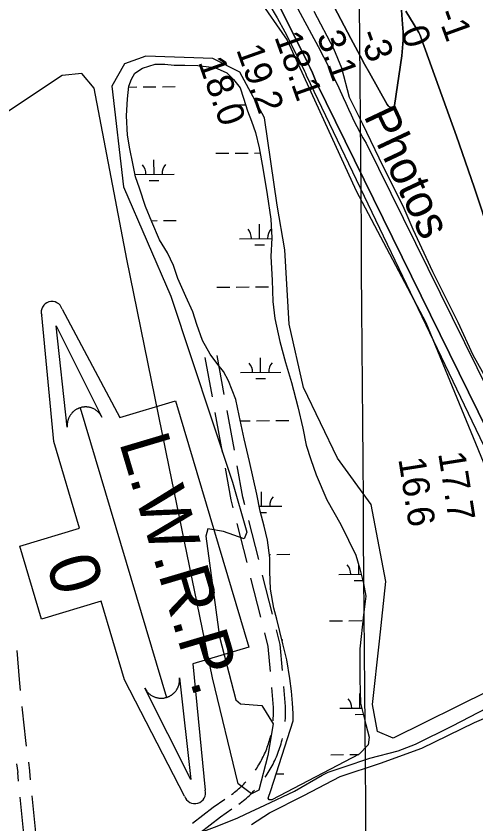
# Model space of a CAD drawing. Extents: x 3540316 to 3578335, y 553172 to 578787.
# Drawn here: x 3548915 to 3550058, y 559700 to 561708 of the extents above; entities that cross this region are included whole.
import ezdxf

# ---------------------------------------------------------------- set-up
doc = ezdxf.new("R2010")
doc.units = 0
for name, color, linetype in [('V-DTCH-CNTR', 7, 'Continuous'), ('V-GRID-MAJR', 7, 'Continuous'), ('V-RIVR-EDGE', 7, 'Continuous'), ('V-RIVR-IDEN', 7, 'Continuous'), ('V-RIVR-RANG', 7, 'Continuous'), ('V-ROAD-CNTR', 7, 'Continuous'), ('V-SITE-VEGE', 7, 'Continuous'), ('V-TOPO-DPTH', 7, 'Continuous'), ('V-TOPO-MINR', 7, 'Continuous'), ('V-TOPO-WATR', 7, 'Continuous'), ('V-TOPO-WATR-IDEN', 7, 'Continuous'), ('V-WETL-SWMP', 7, 'Continuous')]:
    doc.layers.add(name, color=color, linetype=linetype)

msp = doc.modelspace()

# ---------------------------------------------------------------- linework, layer by layer
at = {"layer": 'V-DTCH-CNTR'}
for points in [[(3549485, 559724.9), (3549533.4, 559746.8), (3549607.2, 559781.4), (3549675.8, 559821.1), (3549691.1, 559828.6), (3549730.9, 559841.8), (3549794.2, 559863.8), (3549865, 559882.3), (3549908.4, 559898.3), (3550000.5, 559944), (3550086.8, 559988.4), (3550165.2, 560026.6), (3550230.1, 560057.2)], [(3549012.5, 559549), (3549102.4, 559580.2), (3549225.7, 559624.1), (3549334.7, 559665.2), (3549361.7, 559675.1), (3549415.1, 559694.7), (3549466.2, 559715.4), (3549485, 559724.9)]]:
    msp.add_lwpolyline(points, dxfattribs=at)
at = {"layer": 'V-GRID-MAJR'}
msp.add_spline([(3549793, 558613.9), (3549748.1, 564672.9), (3549703.1, 570733.8), (3549658.2, 576794.8), (3549658.2, 576796.7)], degree=3, dxfattribs=at)
at = {"layer": 'V-RIVR-EDGE'}
msp.add_lwpolyline([(3549655.4, 561719.8), (3549704.4, 561627.2), (3549724.1, 561579.2), (3549743.1, 561506.5), (3549776.6, 561439.8), (3549827.3, 561335.2), (3549876.3, 561236.6), (3549901.4, 561178.3), (3549950.4, 561073.1), (3550013.7, 560947.5), (3550050.7, 560866.4), (3550104.5, 560769.6)], dxfattribs=at)
at = {"layer": 'V-ROAD-CNTR'}
for points in [[(3549403, 560761.8), (3549385.3, 560859.4)], [(3549432.5, 560767.2), (3549414.8, 560864.7)], [(3549428, 560624.1), (3549410.1, 560722.5)], [(3549457.5, 560629.4), (3549439.7, 560727.8)], [(3549483.7, 560493), (3549478.8, 560512), (3549464.7, 560590.1)], [(3549454.6, 560485.6), (3549449.5, 560505.6), (3549435.1, 560584.7)], [(3549518.1, 560357.3), (3549493.5, 560454.2)], [(3549489, 560349.9), (3549464.4, 560446.8)], [(3549523.4, 560214.2), (3549498.8, 560311.1)], [(3549552.5, 560221.6), (3549527.9, 560318.5)], [(3549547.1, 560079.2), (3549542, 560141), (3549533.2, 560175.4)], [(3549577, 560081.7), (3549571.6, 560146), (3549562.3, 560182.8)], [(3548916.2, 560131.2), (3548922.2, 560059.5), (3548924.8, 560031.8)], [(3549554.5, 559989.5), (3549550.4, 560039.3)], [(3549584.4, 559992), (3549580.3, 560041.8)], [(3548928.6, 559992), (3548929.4, 559983.6), (3548937.9, 559907.8), (3548939.9, 559893.2)], [(3549553.9, 559956.8), (3549554.1, 559959.5), (3549554.4, 559963.9), (3549554.6, 559968.3), (3549554.7, 559972.7), (3549554.8, 559977.1), (3549554.8, 559981.5), (3549554.6, 559985.8), (3549554.5, 559990.2)], [(3549583.8, 559954.5), (3549584.1, 559957.4), (3549584.4, 559962.3), (3549584.6, 559967.2), (3549584.7, 559972.1), (3549584.8, 559977), (3549584.8, 559982), (3549584.6, 559986.9), (3549584.4, 559991.3)], [(3549509.8, 559833.9), (3549511.5, 559836.4), (3549513.9, 559840), (3549516.3, 559843.7), (3549518.6, 559847.5), (3549520.8, 559851.2), (3549523, 559855.1), (3549525.1, 559858.9), (3549527.1, 559862.8), (3549529.1, 559866.7), (3549531, 559870.7), (3549532.8, 559874.7), (3549534.6, 559878.7), (3549536.3, 559882.8), (3549537.9, 559886.8), (3549539.4, 559891), (3549540.9, 559895.1), (3549542.3, 559899.3), (3549543.6, 559903.5), (3549544.9, 559907.7), (3549546.1, 559911.9), (3549547.2, 559916.2), (3549548.1, 559919.7)], [(3549534.5, 559816.8), (3549536.3, 559819.5), (3549539.1, 559823.6), (3549541.7, 559827.8), (3549544.3, 559831.9), (3549546.8, 559836.2), (3549549.2, 559840.5), (3549551.6, 559844.8), (3549553.8, 559849.1), (3549556.1, 559853.5), (3549558.2, 559858), (3549560.2, 559862.4), (3549562.2, 559866.9), (3549564.1, 559871.5), (3549565.9, 559876.1), (3549567.6, 559880.7), (3549569.3, 559885.3), (3549570.8, 559890), (3549572.3, 559894.7), (3549573.7, 559899.3), (3549575.1, 559904.1), (3549576.3, 559908.9), (3549577.2, 559912.6)], [(3548915.6, 559849.5), (3548918.5, 559827.8)], [(3548945.3, 559853.6), (3548948.2, 559831.8)], [(3548920.6, 559806.7), (3548918.5, 559828.3)], [(3548950.4, 559809.7), (3548948.3, 559831.3)], [(3549450.6, 559773.5), (3549454.2, 559776.2), (3549457.6, 559778.8), (3549461.1, 559781.6), (3549464.5, 559784.4), (3549467.8, 559787.2), (3549471.1, 559790.1), (3549474.4, 559793.1), (3549477.6, 559796.1), (3549480.7, 559799.1), (3549483.8, 559802.3), (3549486.1, 559804.7)], [(3548934.3, 559667.4), (3548924.5, 559766.9)], [(3548964.2, 559670.4), (3548954.4, 559769.9)], [(3549468.3, 559749.3), (3549472.2, 559752.2), (3549476.1, 559755.2), (3549479.9, 559758.2), (3549483.7, 559761.3), (3549487.5, 559764.5), (3549491.1, 559767.8), (3549494.8, 559771.1), (3549498.4, 559774.5), (3549501.9, 559777.9), (3549505.4, 559781.4), (3549507.8, 559784)], [(3549353.3, 559701.9), (3549405.1, 559741.7), (3549434, 559761.9)], [(3549371.5, 559678.1), (3549422.8, 559717.5), (3549451.2, 559737.4)]]:
    msp.add_lwpolyline(points, dxfattribs=at)
at = {"layer": 'V-SITE-VEGE'}
for p, q in [((3549317.9, 562039.3), (3549589, 561647.7)), ((3549589, 561647.7), (3549760.5, 561274)), ((3549237.5, 561608.3), (3549184.4, 561589.4)), ((3549404.1, 561602.5), (3549237.5, 561608.3)), ((3549471.5, 561568.2), (3549404.1, 561602.5)), ((3549184.4, 561589.4), (3549152.3, 561533.7)), ((3549029.5, 561560.6), (3548829, 561427.3)), ((3549078.1, 561565.6), (3549029.5, 561560.6)), ((3549108.4, 561528.8), (3549078.1, 561565.6)), ((3549532.4, 561455.2), (3549471.5, 561568.2)), ((3549152.3, 561533.7), (3549181.8, 561283.9)), ((3549190, 561103.5), (3549108.4, 561528.8)), ((3549564, 561237.9), (3549532.4, 561455.2)), ((3549181.8, 561283.9), (3549299.4, 561011.6)), ((3549760.5, 561274), (3549933.9, 560946.5)), ((3549583.2, 561127), (3549564, 561237.9)), ((3549593.8, 560941.9), (3549583.2, 561127)), ((3549295.3, 560588.1), (3549190, 561103.5)), ((3549299.4, 561011.6), (3549452.9, 560549.8)), ((3549629.5, 560784.7), (3549593.8, 560941.9)), ((3549933.9, 560946.5), (3550148.1, 560424.9)), ((3549714, 560609.4), (3549629.5, 560784.7)), ((3549798.1, 560494.3), (3549714, 560609.4)), ((3549403, 560063.4), (3549295.3, 560588.1)), ((3549452.9, 560549.8), (3549488.5, 560425.1)), ((3549834.2, 560302.4), (3549798.1, 560494.3)), ((3549391.2, 560433.7), (3549386.7, 560415.1)), ((3549430.6, 560427), (3549391.2, 560433.7)), ((3549386.7, 560415.1), (3549420.8, 560165.4)), ((3549481.6, 560408.8), (3549430.6, 560427)), ((3549488.5, 560425.1), (3549481.6, 560408.8)), ((3549819, 560154.2), (3549834.2, 560302.4)), ((3549420.8, 560165.4), (3549461.2, 560008.3)), ((3549801.5, 559996.7), (3549819, 560154.2)), ((3549467.3, 559800), (3549403, 560063.4)), ((3550090.6, 560031.1), (3549853, 559913.7)), ((3550055.2, 559952.1), (3550238.7, 560032.1)), ((3549461.2, 560008.3), (3549472.9, 559999.1)), ((3549472.9, 559999.1), (3549526.1, 559994.8)), ((3549526.1, 559994.8), (3549554.2, 559948.8)), ((3549813.5, 559929.7), (3549801.5, 559996.7)), ((3549554.2, 559948.8), (3549540.8, 559870)), ((3549924.3, 559888.2), (3550055.2, 559952.1)), ((3549853, 559913.7), (3549813.5, 559929.7)), ((3549821, 559851.6), (3549924.3, 559888.2)), ((3549540.8, 559870), (3549518.3, 559784.2)), ((3549721.1, 559818), (3549821, 559851.6)), ((3549630, 559771.1), (3549721.1, 559818)), ((3549499.8, 559774.8), (3549467.3, 559800)), ((3549518.3, 559784.2), (3549499.8, 559774.8)), ((3549544.7, 559727.7), (3549630, 559771.1)), ((3549499.8, 559699), (3549544.7, 559727.7))]:
    msp.add_line(p, q, dxfattribs=at)
at = {"layer": 'V-TOPO-DPTH'}
for points in [[(3549873.2, 561722.5), (3549876.1, 561687.9), (3549877.1, 561668.2), (3549877.2, 561648.6), (3549876, 561629), (3549873.9, 561609.4), (3549856.3, 561485.7), (3549855.2, 561483.1), (3549853.5, 561481.2), (3549851.1, 561480.3), (3549848.3, 561480.1), (3549845, 561481.3), (3549842.1, 561482.9), (3549839.8, 561485.2), (3549837.7, 561487.9), (3549793.5, 561567), (3549781.7, 561588.2), (3549770.1, 561609.4), (3549758.7, 561630.7), (3549747.4, 561652), (3549581.8, 561967.8)], [(3549581.8, 561967.8), (3549747.4, 561652), (3549758.7, 561630.7), (3549770.1, 561609.4), (3549781.7, 561588.2), (3549793.5, 561567), (3549837.7, 561487.9), (3549839.8, 561485.2), (3549842.1, 561482.9), (3549845, 561481.3), (3549848.3, 561480.1), (3549851.1, 561480.3), (3549853.5, 561481.2), (3549855.2, 561483.1), (3549856.3, 561485.7), (3549873.9, 561609.4), (3549876, 561629), (3549877.2, 561648.6), (3549877.1, 561668.2), (3549876.1, 561687.9), (3549873.2, 561722.5)], [(3550158.9, 560532.2), (3549661.8, 561541.8), (3549656.9, 561554.4), (3549651.8, 561566.8), (3549646.3, 561579.1), (3549640.5, 561591.2), (3549558.2, 561757)], [(3550096.2, 561154.8), (3550054.2, 561282.5), (3550010.2, 561409.6), (3549922.5, 561653.2), (3549920.6, 561657.9), (3549918.6, 561662.5), (3549916.3, 561667), (3549913.8, 561671.4), (3549884.4, 561720.3)], [(3549884.4, 561720.3), (3549913.8, 561671.4), (3549916.3, 561667), (3549918.6, 561662.5), (3549920.6, 561657.9), (3549922.5, 561653.2), (3550010.2, 561409.6), (3550054.2, 561282.5), (3550096.2, 561154.8)]]:
    msp.add_lwpolyline(points, dxfattribs=at)
at = {"layer": 'V-TOPO-MINR'}
for points in [[(3549420.2, 562087), (3549665.8, 561632.5), (3549679.3, 561607), (3549692.5, 561581.3), (3549705.2, 561555.4), (3549717.5, 561529.3), (3549728.3, 561506), (3549735, 561491.5), (3549741.7, 561476.9), (3549748.4, 561462.4), (3549755, 561447.9), (3549762, 561433.5), (3549769.3, 561419.3), (3549777.3, 561405.5), (3549785.6, 561391.9), (3550183.1, 560586.4)], [(3549558.2, 561757), (3549640.5, 561591.2), (3549646.3, 561579.1), (3549651.8, 561566.8), (3549656.9, 561554.4), (3549661.8, 561541.8), (3550158.9, 560532.2)], [(3549543.5, 561738.6), (3549563.7, 561704), (3549582.8, 561668.8), (3549601.1, 561633.2), (3549632.2, 561570.7), (3549634.4, 561566.1), (3549636.4, 561561.3), (3550125.1, 560541.6)]]:
    msp.add_lwpolyline(points, dxfattribs=at)
at = {"layer": 'V-TOPO-WATR'}
for points in [[(3549581.8, 561967.8), (3549747.4, 561652), (3549758.7, 561630.7), (3549770.1, 561609.4), (3549781.7, 561588.2), (3549793.5, 561567), (3549837.7, 561487.9), (3549839.8, 561485.2), (3549842.1, 561482.9), (3549845, 561481.3), (3549848.3, 561480.1), (3549851.1, 561480.3), (3549853.5, 561481.2), (3549855.2, 561483.1), (3549856.3, 561485.7), (3549873.9, 561609.4), (3549876, 561629), (3549877.2, 561648.6), (3549877.1, 561668.2), (3549876.1, 561687.9), (3549873.2, 561722.5)], [(3549884.4, 561720.3), (3549913.8, 561671.4), (3549916.3, 561667), (3549918.6, 561662.5), (3549920.6, 561657.9), (3549922.5, 561653.2), (3550010.2, 561409.6), (3550054.2, 561282.5), (3550096.2, 561154.8)]]:
    msp.add_lwpolyline(points, dxfattribs=at)
at = {"layer": 'V-TOPO-WATR-IDEN'}
msp.add_line((3549074.3, 560734.7), (3549288.5, 560014.6), dxfattribs=at)
for points in [[(3549029, 560979.9), (3549172.6, 560710.3), (3549311.3, 560751.5), (3549493.3, 560139.5), (3549354.6, 560098.2), (3549384.6, 559784.5)], [(3549333.8, 559769.4), (3549184.4, 560058.7), (3549126.4, 560253.6), (3548977.5, 560209.4), (3548923.6, 560390.6), (3549072.5, 560434.9), (3549008.4, 560650.4), (3548978.2, 560964.8)]]:
    msp.add_lwpolyline(points, dxfattribs=at)
for points in [[(3549041.9, 560685.9), (3549013.8, 560938.2), (3549128.2, 560711.5), (3549125.9, 560715.5), (3549123.3, 560719.1), (3549122.2, 560720.5), (3549121.2, 560721.6), (3549119.9, 560723), (3549118.6, 560724.3), (3549117.4, 560725.3), (3549115.7, 560726.7), (3549113.8, 560728.1), (3549112.8, 560728.9), (3549111.3, 560729.8), (3549109.4, 560730.9), (3549107.9, 560731.7), (3549106.2, 560732.5), (3549105.1, 560733), (3549103.9, 560733.5), (3549102.3, 560734), (3549100.9, 560734.5), (3549099.5, 560734.9), (3549098.3, 560735.2), (3549096.5, 560735.6), (3549094.8, 560736), (3549093.4, 560736.2), (3549091.7, 560736.3), (3549090.3, 560736.5), (3549089, 560736.5), (3549088, 560736.6), (3549086.5, 560736.5), (3549085, 560736.5), (3549083.5, 560736.4), (3549082, 560736.2), (3549080.7, 560736.1), (3549079.2, 560735.8), (3549078, 560735.6), (3549076.2, 560735.2), (3549074.3, 560734.7), (3549073.7, 560734.5), (3549072.8, 560734.2), (3549071.8, 560733.8), (3549070.8, 560733.4), (3549069.8, 560733.1), (3549068.9, 560732.7), (3549067.8, 560732.2), (3549067.1, 560731.8), (3549066, 560731.3), (3549065, 560730.7), (3549064.3, 560730.3), (3549062.6, 560729.3), (3549061.7, 560728.7), (3549061.1, 560728.3), (3549060.1, 560727.5), (3549059.2, 560726.9), (3549058.3, 560726.2), (3549057.3, 560725.3), (3549056.4, 560724.5), (3549055.7, 560723.8), (3549055.1, 560723.2), (3549054.3, 560722.4), (3549053.6, 560721.6), (3549052.8, 560720.7), (3549052, 560719.8), (3549051.2, 560718.8), (3549050.3, 560717.6), (3549049.7, 560716.7), (3549049, 560715.7), (3549048.3, 560714.7), (3549047.8, 560713.8), (3549047.3, 560712.9), (3549046.6, 560711.5), (3549046.6, 560711.5), (3549046.1, 560710.6), (3549045.8, 560710), (3549045.4, 560709.1), (3549044.9, 560707.9), (3549044.6, 560706.9), (3549044.2, 560706.1), (3549043.9, 560704.9), (3549043.5, 560703.8), (3549043.3, 560703.1), (3549043, 560702), (3549042.7, 560700.6), (3549042.5, 560699.8), (3549042.4, 560699.1), (3549042.3, 560698.5), (3549042.2, 560697.8), (3549042, 560696.8), (3549041.9, 560695.8), (3549041.8, 560694.8), (3549041.7, 560693.9), (3549041.7, 560692.6), (3549041.6, 560691.9), (3549041.6, 560690.7), (3549041.7, 560689.3), (3549041.7, 560688.3), (3549041.7, 560687.5), (3549041.8, 560686.8), (3549041.9, 560686.2)], [(3549320.9, 560063.4), (3549349.1, 559811), (3549234.7, 560037.7), (3549236.9, 560033.8), (3549239.5, 560030.2), (3549240.6, 560028.8), (3549241.7, 560027.6), (3549243, 560026.3), (3549244.3, 560025), (3549245.5, 560023.9), (3549247.1, 560022.6), (3549249, 560021.2), (3549250.1, 560020.4), (3549251.5, 560019.5), (3549253.4, 560018.4), (3549254.9, 560017.6), (3549256.6, 560016.8), (3549257.7, 560016.3), (3549259, 560015.8), (3549260.5, 560015.3), (3549261.9, 560014.8), (3549263.4, 560014.4), (3549264.6, 560014.1), (3549266.3, 560013.6), (3549268.1, 560013.3), (3549269.5, 560013.1), (3549271.1, 560012.9), (3549272.5, 560012.8), (3549273.8, 560012.8), (3549274.8, 560012.7), (3549276.3, 560012.7), (3549277.8, 560012.8), (3549279.3, 560012.9), (3549280.8, 560013), (3549282.2, 560013.2), (3549283.6, 560013.5), (3549284.9, 560013.7), (3549286.6, 560014.1), (3549288.5, 560014.6), (3549289.1, 560014.8), (3549290, 560015.1), (3549291, 560015.5), (3549292, 560015.8), (3549293, 560016.2), (3549293.9, 560016.6), (3549295, 560017.1), (3549295.7, 560017.5), (3549296.8, 560018), (3549297.8, 560018.6), (3549298.5, 560019), (3549300.2, 560020), (3549301.1, 560020.6), (3549301.7, 560021), (3549302.7, 560021.8), (3549303.6, 560022.4), (3549304.5, 560023.1), (3549305.5, 560024), (3549306.5, 560024.8), (3549307.2, 560025.5), (3549307.8, 560026.1), (3549308.6, 560026.9), (3549309.3, 560027.7), (3549310.1, 560028.6), (3549310.8, 560029.5), (3549311.6, 560030.4), (3549312.5, 560031.7), (3549313.2, 560032.6), (3549313.9, 560033.6), (3549314.5, 560034.6), (3549315, 560035.5), (3549315.5, 560036.4), (3549316.3, 560037.8), (3549316.3, 560037.8), (3549316.7, 560038.7), (3549317, 560039.3), (3549317.4, 560040.2), (3549317.9, 560041.4), (3549318.3, 560042.4), (3549318.6, 560043.2), (3549319, 560044.4), (3549319.3, 560045.4), (3549319.5, 560046.2), (3549319.8, 560047.2), (3549320.1, 560048.7), (3549320.3, 560049.5), (3549320.4, 560050.2), (3549320.6, 560050.8), (3549320.7, 560051.5), (3549320.8, 560052.5), (3549320.9, 560053.5), (3549321, 560054.4), (3549321.1, 560055.4), (3549321.2, 560056.7), (3549321.2, 560057.4), (3549321.2, 560058.6), (3549321.2, 560060), (3549321.1, 560061), (3549321.1, 560061.8), (3549321, 560062.5), (3549321, 560063)]]:
    msp.add_lwpolyline(points, close=True, dxfattribs=at)
for centre, start, end in [((3549003.6, 560972.3), 16.5648, 196.5648), ((3549359.2, 559777), 196.5648, 16.5648)]:
    msp.add_arc(centre, 26.5, start, end, dxfattribs=at)
at = {"layer": 'V-WETL-SWMP'}
for p, q in [((3549195, 561531.7), (3549214.5, 561531.9)), ((3549230.5, 561532), (3549262.5, 561532.2)), ((3549278.5, 561532.4), (3549310.5, 561532.6)), ((3549467.7, 561487.4), (3549485.7, 561487.5)), ((3549257.6, 561315), (3549257.3, 561351)), ((3549411.8, 561366.9), (3549443.8, 561367.1)), ((3549459.8, 561367.3), (3549491.8, 561367.5)), ((3549507.8, 561367.6), (3549521.7, 561367.7)), ((3549210.5, 561314.6), (3549307.6, 561315.3)), ((3549245.7, 561299.4), (3549269.7, 561299.6)), ((3549251.1, 561199.5), (3549265.1, 561199.6)), ((3549281.1, 561199.7), (3549313.1, 561200)), ((3549520.3, 561155.1), (3549520, 561191.1)), ((3549470.3, 561154.7), (3549551, 561155.4)), ((3549508.4, 561139.6), (3549532.4, 561139.8)), ((3549414.3, 561034.2), (3549446.3, 561034.5)), ((3549462.3, 561034.6), (3549494.3, 561034.8)), ((3549510.3, 561035), (3549542.3, 561035.2)), ((3549522.8, 560822.5), (3549522.5, 560858.5)), ((3549472.8, 560822.1), (3549572.8, 560822.8)), ((3549510.9, 560806.9), (3549534.9, 560807.1)), ((3549472.4, 560702), (3549496.9, 560702.2)), ((3549512.9, 560702.3), (3549544.9, 560702.5)), ((3549560.9, 560702.7), (3549592.9, 560702.9)), ((3549525.4, 560489.8), (3549525.1, 560525.8)), ((3549519.1, 560489.7), (3549575.4, 560490.2)), ((3549522.3, 560474.3), (3549537.5, 560474.4)), ((3549544.4, 560369.9), (3549547.5, 560369.9)), ((3549563.5, 560370), (3549595.5, 560370.3)), ((3549767.2, 560320.8), (3549767, 560342.8)), ((3549717.2, 560320.4), (3549773, 560320.9)), ((3549755.3, 560305.3), (3549777.1, 560305.5)), ((3549694.6, 560204.8), (3549726.6, 560205.1)), ((3549742.6, 560205.2), (3549774.6, 560205.5)), ((3549575.9, 560157.5), (3549577.9, 560157.5)), ((3549769.7, 559988.2), (3549769.5, 560024.2)), ((3549719.7, 559987.8), (3549774.5, 559988.2)), ((3549757.8, 559972.6), (3549778.2, 559972.8)), ((3549697.2, 559872.2), (3549729.2, 559872.4)), ((3549745.2, 559872.5), (3549767.3, 559872.7)), ((3549561.5, 559824.7), (3549580.5, 559824.8))]:
    msp.add_line(p, q, dxfattribs=at)
msp.add_lwpolyline([(3549548.1, 559783.2), (3549604.2, 559956.8), (3549604.1, 559970.4), (3549604.1, 559974.5), (3549602.5, 560000.4), (3549599.6, 560030.4), (3549595.3, 560061.7), (3549588.2, 560108.1), (3549578.4, 560147.6), (3549562.9, 560208.8), (3549555.9, 560236.1), (3549547.4, 560283.8), (3549545.8, 560327.4), (3549545.5, 560361.5), (3549539.8, 560405.1), (3549531.4, 560440.5), (3549521.6, 560477.3), (3549513.1, 560519.5), (3549504.6, 560560.4), (3549494.8, 560601.2), (3549482.1, 560657.1), (3549469.5, 560715.6), (3549461, 560755.1), (3549443, 560801.4), (3549430.5, 560824.5), (3549416.8, 560842.1), (3549397.5, 560867.9), (3549378.2, 560901.9), (3549364.3, 560941.3), (3549354.5, 560972.6), (3549336.5, 561010.7), (3549317.1, 561055.6), (3549306, 561088.3), (3549290.8, 561119.5), (3549271.5, 561152.1), (3549252.1, 561197), (3549236.8, 561235.1), (3549221.5, 561280), (3549211.8, 561308.6), (3549204.7, 561341.3), (3549197.6, 561378.1), (3549192, 561412.1), (3549188.9, 561459.8), (3549191.3, 561502.1), (3549195.2, 561533.5), (3549201.9, 561551.3), (3549210, 561566.4), (3549229, 561578.8), (3549260.3, 561588.5), (3549284.9, 561588.7), (3549308.1, 561586.1), (3549334, 561586.3), (3549366.7, 561585.2), (3549400.9, 561581.3), (3549414.5, 561577.3), (3549439.2, 561566.6), (3549455.6, 561550.3), (3549472.1, 561530), (3549480.5, 561504.1), (3549490.3, 561472.8), (3549500, 561446.9), (3549509.7, 561418.4), (3549519.5, 561380.2), (3549528.1, 561329.8), (3549539.4, 561264.4), (3549548, 561203.1), (3549551.1, 561156.8), (3549548.6, 561110.4), (3549551.8, 561051.7), (3549553.5, 560998.5), (3549557.9, 560956.3), (3549570.5, 560899.1), (3549584.5, 560847.3), (3549599.9, 560797), (3549615.3, 560737.1), (3549627.9, 560684), (3549636.4, 560641.7), (3549647.5, 560606.3), (3549661.4, 560568.2), (3549687.8, 560505.7), (3549722.3, 560444.5), (3549741.7, 560405.1), (3549759.6, 560368.4), (3549769.4, 560334.4), (3549779.2, 560297.6), (3549784.9, 560266.3), (3549778.4, 560219.8), (3549769.4, 560135.2), (3549769.9, 560060.2), (3549771.7, 560000.2), (3549784.3, 559947.1), (3549792.7, 559915.8), (3549790.1, 559896.7), (3549768.4, 559873.3), (3549551, 559760), (3549544.1, 559760), (3549541.4, 559764)], close=True, dxfattribs=at)
for centre, start, end in [((3549202.3, 561315), 359.6699, 41.2135), ((3549312.8, 561315.9), 139.6699, 181.2135), ((3549465, 561155.2), 359.6699, 41.2135), ((3549575.5, 561156), 139.6699, 181.2135), ((3549467.6, 560822.5), 359.6699, 41.2135), ((3549578.1, 560823.4), 139.6699, 181.2135), ((3549580.6, 560490.7), 139.6699, 181.2135), ((3549711.9, 560320.9), 359.6699, 41.2135), ((3549714.5, 559988.2), 359.6699, 41.2135)]:
    msp.add_arc(centre, 35.2, start, end, dxfattribs=at)

# ---------------------------------------------------------------- texts
at = {"layer": 'V-RIVR-IDEN'}
msp.add_text('Photos', height=83, rotation=295.1859, dxfattribs=at).set_placement((3549778.2, 561459.9))
at = {"layer": 'V-RIVR-RANG'}
for s, rotation, p in [('-1', 289.8741, (3549960.1, 561714.9)), ('3.1', 289.5883, (3549661.8, 561658.8)), ('0', 289.8741, (3549869.9, 561670.2)), ('18.1', 289.5883, (3549556.5, 561656.4)), ('-3', 289.8741, (3549766, 561663.5)), ('19.2', 289.5883, (3549461.6, 561624.8)), ('18.0', 289.5883, (3549366.5, 561593.8)), ('17.7', 278.9583, (3549964.4, 560621.3)), ('16.6', 278.9583, (3549865.3, 560607.3))]:
    msp.add_text(s, height=67, rotation=rotation, dxfattribs=at).set_placement(p)
at = {"layer": 'V-TOPO-WATR-IDEN'}
for s, rotation, p in [('L.W.R.P.', 286.5647, (3549170.2, 560649.3)), ('0', 286.5648, (3548988.5, 560349.7))]:
    msp.add_text(s, height=124.5, rotation=rotation, dxfattribs=at).set_placement(p)

doc.saveas('drawing.dxf')
